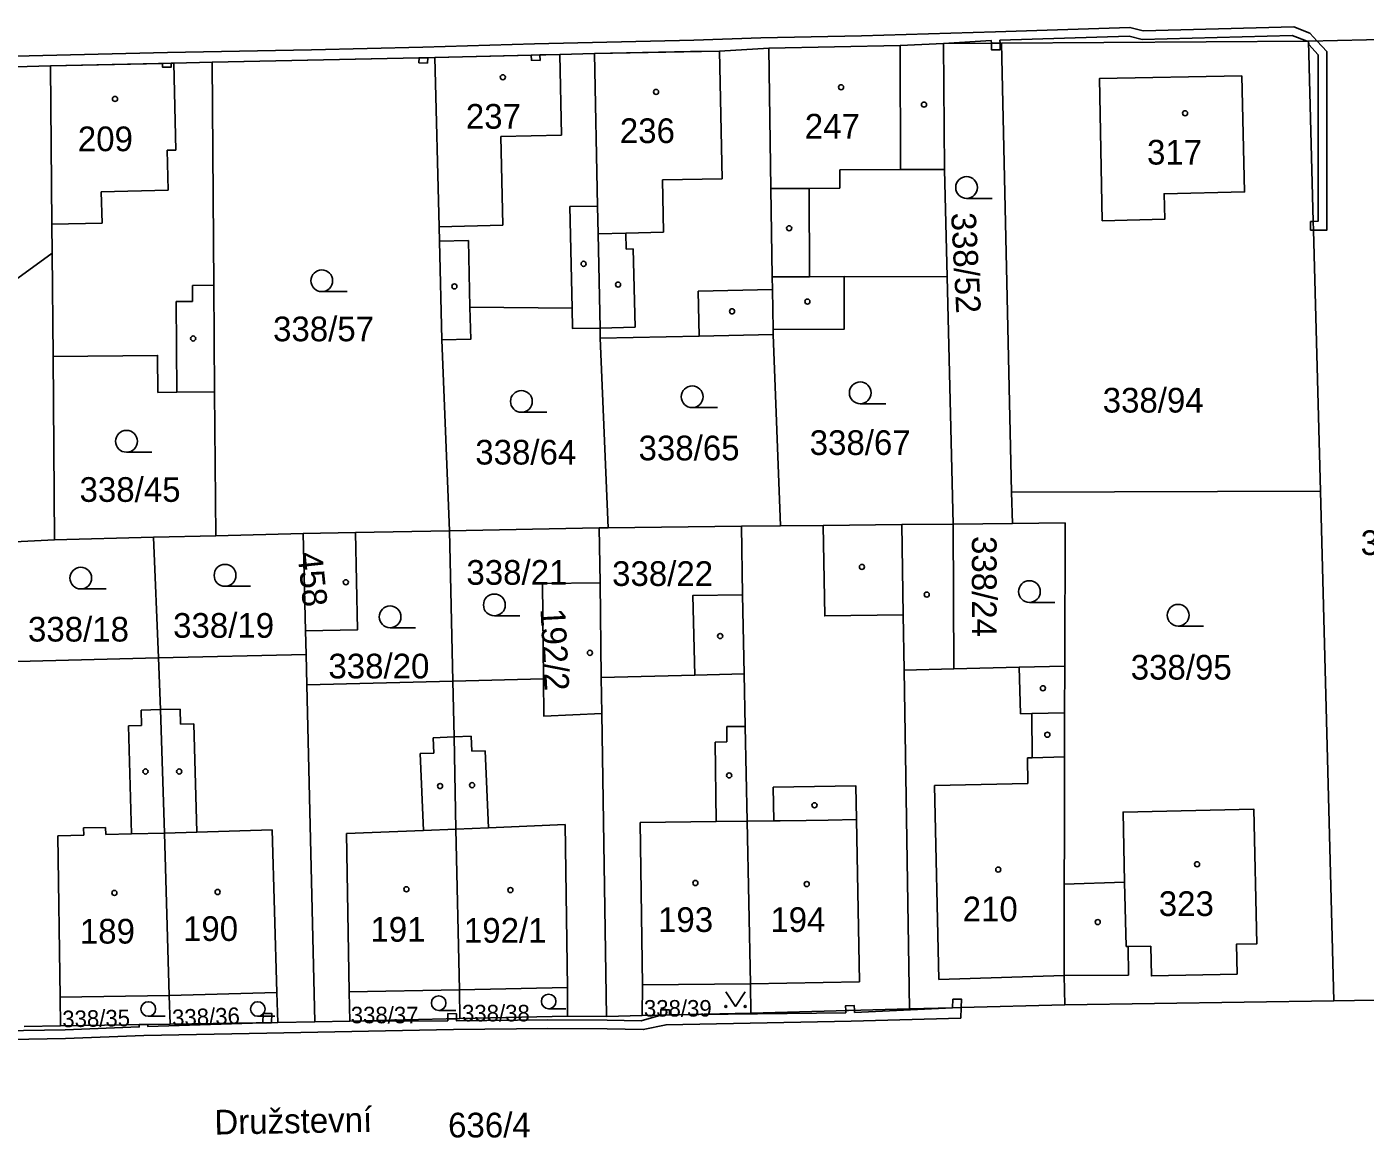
# Model space of a CAD drawing. Extents: x -758582 to -751794, y -998770 to -994350.
# Drawn here: x -755856.2 to -755764, y -995339.9 to -995263.3 of the extents above; entities that cross this region are included whole.
import ezdxf

# ---------------------------------------------------------------- set-up
doc = ezdxf.new("R2010")
doc.units = 0
for name, color, linetype in [('Hranice parcel', 7, 'Continuous'), ('Parcelní čísla', 7, 'Continuous'), ('Pop  PČ popisy', 7, 'Continuous'), ('Vnitřní kresba', 7, 'Continuous'), ('Věcná břemena k části', 7, 'Continuous'), ('Značky budov', 7, 'Continuous'), ('Značky kultur', 7, 'Continuous')]:
    doc.layers.add(name, color=color, linetype=linetype)

msp = doc.modelspace()

# ---------------------------------------------------------------- linework, layer by layer
at = {"layer": 'Hranice parcel'}
for p, q in [((-755755.71, -995264.05), (-755767.91, -995264.33)), ((-755789.06, -995264.46), (-755793.04, -995264.49)), ((-755767.91, -995264.33), (-755789.06, -995264.46)), ((-755788.36, -995295.38), (-755789.06, -995264.46)), ((-755828.06, -995265.45), (-755843.39, -995265.77)), ((-755854.4, -995278.93), (-755854.34, -995286.03)), ((-755792.79, -995280.56), (-755792.37, -995297.58)), ((-755816.68, -995284.08), (-755816.67, -995284.78)), ((-755804.77, -995284.52), (-755804.78, -995284.17)), ((-755827.04, -995298.05), (-755827.58, -995284.89)), ((-755816.12, -995297.84), (-755816.67, -995284.78)), ((-755804.27, -995297.7), (-755804.77, -995284.52)), ((-755854.25, -995298.66), (-755854.34, -995286.03)), ((-755843.14, -995298.39), (-755843.22, -995288.48)), ((-755788.36, -995295.38), (-755767.1, -995295.32)), ((-755788.29, -995297.54), (-755788.36, -995295.38)), ((-755766.18, -995330.42), (-755767.1, -995295.32)), ((-755837.12, -995298.24), (-755843.14, -995298.39)), ((-755833.52, -995298.17), (-755837.12, -995298.24)), ((-755837.12, -995298.24), (-755836.96, -995304.94)), ((-755827.04, -995298.05), (-755833.52, -995298.17)), ((-755816.74, -995297.85), (-755827.04, -995298.05)), ((-755826.82, -995308.39), (-755827.04, -995298.05)), ((-755816.12, -995297.84), (-755816.74, -995297.85)), ((-755816.69, -995301.62), (-755816.74, -995297.85)), ((-755806.96, -995297.73), (-755816.12, -995297.84)), ((-755804.27, -995297.7), (-755806.96, -995297.73)), ((-755806.96, -995297.73), (-755806.87, -995302.46)), ((-755792.37, -995297.58), (-755795.92, -995297.62)), ((-755788.29, -995297.54), (-755792.37, -995297.58)), ((-755854.25, -995298.66), (-755856.99, -995298.8)), ((-755847.42, -995298.49), (-755854.25, -995298.66)), ((-755843.14, -995298.39), (-755847.42, -995298.49)), ((-755847.08, -995306.8), (-755847.42, -995298.49)), ((-755816.69, -995301.62), (-755816.6, -995308.14)), ((-755836.92, -995306.56), (-755836.96, -995304.94)), ((-755847.08, -995306.8), (-755856.82, -995307.05)), ((-755836.92, -995306.56), (-755847.08, -995306.8)), ((-755836.87, -995308.64), (-755836.92, -995306.56)), ((-755784.71, -995310.58), (-755784.7, -995307.36)), ((-755826.82, -995308.39), (-755836.87, -995308.64)), ((-755826.82, -995308.39), (-755820.59, -995308.24)), ((-755816.6, -995308.14), (-755816.56, -995310.63)), ((-755836.33, -995331.87), (-755836.87, -995308.64)), ((-755816.56, -995310.63), (-755816.25, -995331.5)), ((-755784.71, -995313.61), (-755784.71, -995310.58)), ((-755784.74, -995328.68), (-755784.73, -995322.38)), ((-755780.58, -995322.25), (-755784.73, -995322.38)), ((-755806.33, -995329.25), (-755806.3, -995331.26)), ((-755784.69, -995330.7), (-755784.74, -995328.68)), ((-755846.28, -995332.02), (-755846.34, -995330.05)), ((-755826.33, -995331.64), (-755826.37, -995329.66)), ((-755784.69, -995330.7), (-755766.18, -995330.42)), ((-755766.18, -995330.42), (-755753.96, -995330.21)), ((-755816.25, -995331.5), (-755813.79, -995331.42)), ((-755813.79, -995331.42), (-755806.3, -995331.26)), ((-755806.3, -995331.26), (-755795.39, -995330.96)), ((-755856.32, -995332.17), (-755853.83, -995332.13)), ((-755853.83, -995332.13), (-755846.28, -995332.02)), ((-755846.28, -995332.02), (-755838.87, -995331.91)), ((-755838.87, -995331.91), (-755836.33, -995331.87)), ((-755836.33, -995331.87), (-755833.91, -995331.81)), ((-755833.91, -995331.81), (-755826.33, -995331.64)), ((-755826.33, -995331.64), (-755818.93, -995331.46)), ((-755818.93, -995331.46), (-755816.25, -995331.5))]:
    msp.add_line(p, q, dxfattribs=at)
for points in [[(-755805.06, -995264.8), (-755808.47, -995265), (-755817.08, -995265.18)], [(-755793.04, -995264.49), (-755796.03, -995264.61), (-755805.06, -995264.8)], [(-755804.78, -995284.17), (-755804.82, -995281.42), (-755804.83, -995280.56), (-755804.92, -995274.47), (-755805.06, -995264.8)], [(-755792.79, -995280.56), (-755792.97, -995273.15), (-755793.04, -995264.49)], [(-755767.1, -995295.32), (-755767.57, -995277.33), (-755767.59, -995276.74), (-755767.91, -995264.33)], [(-755843.39, -995265.77), (-755846.03, -995265.83), (-755854.52, -995266.03)], [(-755843.22, -995288.48), (-755843.27, -995281.13), (-755843.39, -995265.77)], [(-755817.08, -995265.18), (-755819.46, -995265.24), (-755828.06, -995265.45)], [(-755828.06, -995265.45), (-755827.77, -995277.1), (-755827.75, -995278.1), (-755827.58, -995284.89)], [(-755817.08, -995265.18), (-755816.86, -995275.68), (-755816.82, -995277.58), (-755816.68, -995284.08)], [(-755854.52, -995266.03), (-755860.15, -995266.18), (-755870.93, -995266.46)], [(-755854.4, -995278.93), (-755854.42, -995276.93), (-755854.52, -995266.03)], [(-755772.5, -995266.71), (-755782.3, -995266.89), (-755782.12, -995276.69), (-755777.82, -995276.59), (-755777.86, -995274.83), (-755772.32, -995274.71), (-755772.5, -995266.71)], [(-755870.36, -995288.31), (-755867.15, -995288.2), (-755854.4, -995278.93)], [(-755804.78, -995284.17), (-755799.88, -995284.15), (-755799.89, -995280.54), (-755792.79, -995280.56)], [(-755827.58, -995284.89), (-755825.58, -995284.84), (-755825.64, -995282.64), (-755818.61, -995282.72), (-755818.58, -995284.12), (-755816.68, -995284.08)], [(-755816.67, -995284.78), (-755809.87, -995284.63), (-755804.77, -995284.52)], [(-755854.34, -995286.03), (-755847.14, -995285.96), (-755847.12, -995288.51), (-755845.82, -995288.5), (-755843.22, -995288.48)], [(-755836.96, -995304.94), (-755833.39, -995304.87), (-755833.52, -995298.17)], [(-755795.92, -995297.62), (-755801.32, -995297.67), (-755804.27, -995297.7)], [(-755795.39, -995330.96), (-755795.76, -995307.63), (-755795.82, -995303.82), (-755795.92, -995297.62)], [(-755784.7, -995307.36), (-755787.83, -995307.44), (-755792.33, -995307.55), (-755792.37, -995297.58)], [(-755784.7, -995307.36), (-755784.68, -995297.5), (-755788.29, -995297.54)], [(-755820.59, -995308.24), (-755820.65, -995301.68), (-755816.69, -995301.62)], [(-755806.87, -995302.46), (-755810.29, -995302.49), (-755810.17, -995307.98), (-755816.6, -995308.14)], [(-755806.33, -995329.25), (-755806.56, -995318.04), (-755806.69, -995311.52), (-755806.76, -995307.9), (-755806.87, -995302.46)], [(-755846.34, -995330.05), (-755846.68, -995318.86), (-755846.94, -995310.36), (-755847.08, -995306.8)], [(-755826.37, -995329.66), (-755826.61, -995318.59), (-755826.74, -995312.23), (-755826.82, -995308.39)], [(-755816.56, -995310.63), (-755820.56, -995310.8), (-755820.59, -995308.24)], [(-755784.73, -995322.38), (-755784.72, -995318.96), (-755784.71, -995313.61)], [(-755780.33, -995326.68), (-755778.78, -995326.65), (-755778.73, -995328.7), (-755772.84, -995328.57), (-755772.88, -995326.52), (-755771.48, -995326.49), (-755771.68, -995317.22), (-755780.68, -995317.41), (-755780.58, -995322.25)], [(-755784.74, -995328.68), (-755780.31, -995328.64), (-755780.33, -995326.68)], [(-755818.93, -995331.46), (-755818.92, -995329.49), (-755826.37, -995329.66)], [(-755813.79, -995331.42), (-755813.77, -995329.31), (-755806.33, -995329.25)], [(-755853.83, -995332.13), (-755853.86, -995330.16), (-755846.34, -995330.05)], [(-755846.34, -995330.05), (-755838.93, -995329.84), (-755838.87, -995331.91)], [(-755833.91, -995331.81), (-755833.95, -995329.79), (-755826.37, -995329.66)], [(-755795.39, -995330.96), (-755792.42, -995330.89), (-755791.82, -995330.87), (-755784.69, -995330.7)]]:
    msp.add_lwpolyline(points, dxfattribs=at)
at = {"layer": 'Vnitřní kresba'}
for p, q in [((-755808.29, -995273.8), (-755808.47, -995265)), ((-755796.03, -995264.61), (-755796, -995273.17)), ((-755845.89, -995271.83), (-755846.03, -995265.83)), ((-755819.46, -995265.24), (-755819.33, -995270.79)), ((-755819.33, -995270.79), (-755823.52, -995270.89)), ((-755823.52, -995270.89), (-755823.37, -995276.99)), ((-755846.49, -995271.84), (-755845.89, -995271.83)), ((-755846.42, -995274.59), (-755846.49, -995271.84)), ((-755800.17, -995273.18), (-755796, -995273.17)), ((-755800.17, -995274.45), (-755800.17, -995273.18)), ((-755796, -995273.17), (-755792.97, -995273.15)), ((-755812.39, -995273.88), (-755808.29, -995273.8)), ((-755812.31, -995277.48), (-755812.39, -995273.88)), ((-755851.02, -995274.7), (-755846.42, -995274.59)), ((-755850.97, -995276.85), (-755851.02, -995274.7)), ((-755804.92, -995274.47), (-755802.29, -995274.46)), ((-755802.29, -995274.46), (-755800.17, -995274.45)), ((-755802.27, -995280.55), (-755802.29, -995274.46)), ((-755816.86, -995275.68), (-755818.76, -995275.72)), ((-755818.61, -995282.72), (-755818.76, -995275.72)), ((-755854.42, -995276.93), (-755850.97, -995276.85)), ((-755823.37, -995276.99), (-755827.77, -995277.1)), ((-755816.82, -995277.58), (-755814.91, -995277.54)), ((-755814.91, -995277.54), (-755812.31, -995277.48)), ((-755814.89, -995278.64), (-755814.91, -995277.54)), ((-755825.75, -995278.05), (-755827.75, -995278.1)), ((-755825.64, -995282.64), (-755825.75, -995278.05)), ((-755814.89, -995278.64), (-755814.4, -995278.63)), ((-755814.4, -995278.63), (-755814.28, -995284.02)), ((-755804.83, -995280.56), (-755802.27, -995280.55)), ((-755799.89, -995280.54), (-755802.27, -995280.55)), ((-755843.27, -995281.13), (-755844.75, -995281.14)), ((-755844.75, -995281.14), (-755844.74, -995282.24)), ((-755804.82, -995281.42), (-755809.93, -995281.53)), ((-755809.93, -995281.53), (-755809.87, -995284.63)), ((-755844.74, -995282.24), (-755845.87, -995282.25)), ((-755845.87, -995282.25), (-755845.82, -995288.5)), ((-755814.28, -995284.02), (-755816.68, -995284.08)), ((-755787.83, -995307.44), (-755787.74, -995310.64)), ((-755810.17, -995307.98), (-755806.76, -995307.9)), ((-755792.33, -995307.55), (-755795.76, -995307.63)), ((-755848.28, -995310.4), (-755846.94, -995310.36)), ((-755848.25, -995311.45), (-755848.28, -995310.4)), ((-755846.94, -995310.36), (-755845.59, -995310.32)), ((-755845.59, -995310.32), (-755845.56, -995311.37)), ((-755787.74, -995310.64), (-755786.97, -995310.62)), ((-755786.97, -995310.62), (-755784.71, -995310.58)), ((-755786.97, -995310.62), (-755786.95, -995313.68)), ((-755849.15, -995311.47), (-755848.25, -995311.45)), ((-755848.94, -995318.92), (-755849.15, -995311.47)), ((-755845.56, -995311.37), (-755844.66, -995311.34)), ((-755844.66, -995311.34), (-755844.45, -995318.79)), ((-755807.97, -995311.52), (-755807.96, -995312.58)), ((-755807.97, -995311.52), (-755806.69, -995311.52)), ((-755828.18, -995312.3), (-755826.74, -995312.23)), ((-755828.18, -995312.3), (-755828.14, -995313.35)), ((-755826.74, -995312.23), (-755825.55, -995312.18)), ((-755825.55, -995312.18), (-755825.51, -995313.23)), ((-755807.96, -995312.58), (-755808.77, -995312.6)), ((-755808.77, -995312.6), (-755808.69, -995318.06)), ((-755828.14, -995313.35), (-755829.06, -995313.38)), ((-755829.06, -995313.38), (-755828.84, -995318.68)), ((-755825.51, -995313.23), (-755824.59, -995313.19)), ((-755824.59, -995313.19), (-755824.37, -995318.49)), ((-755786.95, -995313.68), (-755787.27, -995313.68)), ((-755787.27, -995313.68), (-755787.24, -995315.44)), ((-755786.95, -995313.68), (-755784.71, -995313.61)), ((-755804.76, -995315.71), (-755804.72, -995318.02)), ((-755787.24, -995315.44), (-755793.67, -995315.59)), ((-755793.37, -995328.94), (-755793.67, -995315.59)), ((-755852.24, -995318.51), (-755850.72, -995318.47)), ((-755852.22, -995319.01), (-755852.24, -995318.51)), ((-755850.72, -995318.47), (-755850.7, -995318.97)), ((-755826.61, -995318.59), (-755824.37, -995318.49)), ((-755819.08, -995318.27), (-755824.37, -995318.49)), ((-755818.92, -995329.49), (-755819.08, -995318.27)), ((-755808.69, -995318.06), (-755813.93, -995318.13)), ((-755813.77, -995329.31), (-755813.93, -995318.13)), ((-755808.69, -995318.06), (-755806.56, -995318.04)), ((-755804.72, -995318.02), (-755806.56, -995318.04)), ((-755804.72, -995318.02), (-755804.28, -995318.02)), ((-755799.04, -995317.92), (-755798.82, -995329.1)), ((-755854.02, -995319.06), (-755852.22, -995319.01)), ((-755854.02, -995319.06), (-755853.86, -995330.16)), ((-755850.7, -995318.97), (-755848.94, -995318.92)), ((-755848.94, -995318.92), (-755846.68, -995318.86)), ((-755846.68, -995318.86), (-755844.45, -995318.79)), ((-755844.45, -995318.79), (-755839.25, -995318.64)), ((-755839.25, -995318.64), (-755838.93, -995329.84)), ((-755834.14, -995318.9), (-755828.84, -995318.68)), ((-755834.14, -995318.9), (-755833.95, -995329.79)), ((-755828.84, -995318.68), (-755826.61, -995318.59)), ((-755780.48, -995326.68), (-755780.58, -995322.25)), ((-755780.48, -995326.68), (-755780.33, -995326.68)), ((-755806.33, -995329.25), (-755798.82, -995329.1)), ((-755784.74, -995328.68), (-755793.37, -995328.94))]:
    msp.add_line(p, q, dxfattribs=at)
for points in [[(-755795.82, -995303.82), (-755801.22, -995303.91), (-755801.32, -995297.67)], [(-755799.04, -995317.92), (-755799.09, -995315.6), (-755804.76, -995315.71)], [(-755804.28, -995318.02), (-755802.5, -995317.99), (-755800.99, -995317.96), (-755799.04, -995317.92)]]:
    msp.add_lwpolyline(points, dxfattribs=at)
at = {"layer": 'Věcná břemena k části'}
for points in [[(-755860.15, -995266.18), (-755854.52, -995266.03), (-755846.8, -995265.85), (-755846.2, -995265.83), (-755846.03, -995265.83), (-755843.39, -995265.77), (-755829.14, -995265.47), (-755828.54, -995265.46), (-755828.06, -995265.45), (-755821.43, -995265.29), (-755820.83, -995265.27), (-755819.46, -995265.24), (-755817.08, -995265.18), (-755810.46, -995265.04), (-755809.86, -995265.03), (-755808.47, -995265), (-755805.06, -995264.8), (-755796.03, -995264.61), (-755793.04, -995264.49), (-755789.76, -995264.28), (-755789.75, -995264.47), (-755789.15, -995264.46), (-755789.16, -995264.26), (-755780.27, -995263.98), (-755779.36, -995264.21), (-755769.05, -995263.93), (-755768.02, -995264.33), (-755767.91, -995264.33), (-755767.9, -995264.56), (-755767.26, -995265.27), (-755767.26, -995276.73), (-755767.59, -995276.74), (-755767.57, -995277.33), (-755766.66, -995277.34), (-755766.66, -995265.04), (-755767.32, -995264.32), (-755767.82, -995263.77), (-755768.94, -995263.33), (-755779.29, -995263.61), (-755780.21, -995263.37), (-755789.47, -995263.67), (-755798.68, -995263.96), (-755805.63, -995264.09), (-755810.22, -995264.25), (-755821.21, -995264.51), (-755828.89, -995264.74), (-755836.55, -995264.91), (-755846.47, -995265.11), (-755860.77, -995265.44)], [(-755791.85, -995331.6), (-755791.82, -995330.87), (-755792.42, -995330.89), (-755799.17, -995331.21), (-755799.17, -995331.06), (-755799.77, -995331.08), (-755799.77, -995331.23), (-755811.91, -995331.38), (-755812.51, -995331.39), (-755813.86, -995331.79), (-755816.19, -995331.75), (-755820.29, -995331.72), (-755826.57, -995331.78), (-755826.57, -995331.65), (-755827.17, -995331.66), (-755827.17, -995331.79), (-755833.91, -995331.81), (-755836.33, -995331.87), (-755838.87, -995331.91), (-755839.31, -995331.92), (-755839.91, -995331.93), (-755847.81, -995332.19), (-755847.81, -995332.04), (-755848.41, -995332.05), (-755848.41, -995332.21), (-755853.5, -995332.4), (-755862.11, -995332.55)], [(-755853.48, -995333), (-755848.09, -995332.79), (-755839.63, -995332.63), (-755826.77, -995332.38), (-755820.29, -995332.32), (-755816.2, -995332.35), (-755813.71, -995332.39), (-755812.14, -995332.06), (-755799.39, -995331.82), (-755791.85, -995331.6)], [(-755904.61, -995342.37), (-755904.86, -995335.72), (-755905.71, -995334.02), (-755904.04, -995334.02), (-755891.45, -995333.81), (-755886.34, -995333.63), (-755875.7, -995333.36), (-755870.14, -995333.28), (-755862.36, -995333.16), (-755853.48, -995333)]]:
    msp.add_lwpolyline(points, dxfattribs=at)
for points in [[(-755789.15, -995264.46), (-755789.75, -995264.47), (-755789.75, -995264.91), (-755789.15, -995264.91)], [(-755846.2, -995265.83), (-755846.8, -995265.85), (-755846.8, -995266.12), (-755846.2, -995266.11)], [(-755828.56, -995265.83), (-755828.54, -995265.46), (-755829.14, -995265.47), (-755829.16, -995265.81)], [(-755820.83, -995265.27), (-755821.43, -995265.29), (-755821.41, -995265.64), (-755820.81, -995265.65)], [(-755767.77, -995276.74), (-755767.78, -995277.33), (-755767.57, -995277.33), (-755767.59, -995276.74)], [(-755792.42, -995330.89), (-755791.82, -995330.87), (-755791.8, -995330.31), (-755792.4, -995330.31)], [(-755839.88, -995331.28), (-755839.91, -995331.93), (-755839.31, -995331.92), (-755839.28, -995331.29)], [(-755827.17, -995331.29), (-755827.17, -995331.66), (-755826.57, -995331.65), (-755826.57, -995331.3)], [(-755812.51, -995331.39), (-755811.91, -995331.38), (-755811.91, -995331.04), (-755812.51, -995331.03)], [(-755799.17, -995331.06), (-755799.19, -995330.74), (-755799.79, -995330.75), (-755799.77, -995331.08)]]:
    msp.add_lwpolyline(points, close=True, dxfattribs=at)
at = {"layer": 'Značky budov'}
for centre in [(-755823.377, -995266.809), (-755812.827, -995267.819), (-755800.097, -995267.499), (-755850.077, -995268.299), (-755794.387, -995268.689), (-755776.417, -995269.289), (-755803.667, -995277.209), (-755817.817, -995279.659), (-755826.717, -995281.209), (-755815.447, -995281.089), (-755802.417, -995282.259), (-755807.597, -995282.929), (-755844.697, -995284.799), (-755798.657, -995300.529), (-755834.187, -995301.589), (-755794.197, -995302.439), (-755808.417, -995305.289), (-755817.387, -995306.449), (-755786.197, -995308.889), (-755785.897, -995312.089), (-755847.977, -995314.619), (-755845.657, -995314.619), (-755807.797, -995314.889), (-755827.697, -995315.619), (-755825.497, -995315.559), (-755801.927, -995316.949), (-755789.277, -995321.379), (-755775.587, -995321.009), (-755810.127, -995322.299), (-755802.457, -995322.369), (-755850.117, -995322.979), (-755843.017, -995322.919), (-755830.017, -995322.729), (-755822.857, -995322.789), (-755782.427, -995324.989)]:
    msp.add_circle(centre, 0.175, dxfattribs=at)
at = {"layer": 'Značky kultur'}
for p, q in [((-755791.453, -995275.15), (-755789.703, -995275.15)), ((-755835.843, -995281.57), (-755834.093, -995281.57)), ((-755822.103, -995289.88), (-755820.353, -995289.88)), ((-755810.343, -995289.56), (-755808.593, -995289.56)), ((-755798.773, -995289.29), (-755797.023, -995289.29)), ((-755849.283, -995292.63), (-755847.533, -995292.63)), ((-755842.503, -995301.86), (-755840.753, -995301.86)), ((-755852.433, -995302.05), (-755850.683, -995302.05)), ((-755787.133, -995302.98), (-755785.383, -995302.98)), ((-755823.963, -995303.9), (-755822.213, -995303.9)), ((-755776.893, -995304.61), (-755775.143, -995304.61)), ((-755831.143, -995304.72), (-755829.393, -995304.72)), ((-755827.795, -995331.07), (-755826.623, -995331.07)), ((-755820.225, -995330.96), (-755819.053, -995330.96)), ((-755847.785, -995331.48), (-755846.613, -995331.48)), ((-755840.245, -995331.48), (-755839.073, -995331.48))]:
    msp.add_line(p, q, dxfattribs=at)
msp.add_lwpolyline([(-755808.03, -995329.794), (-755807.36, -995330.8), (-755806.69, -995329.794)], dxfattribs=at)
for centre, radius in [((-755791.453, -995274.4), 0.75), ((-755835.843, -995280.82), 0.75), ((-755810.343, -995288.81), 0.75), ((-755798.773, -995288.54), 0.75), ((-755822.103, -995289.13), 0.75), ((-755849.283, -995291.88), 0.75), ((-755852.433, -995301.3), 0.75), ((-755842.503, -995301.11), 0.75), ((-755787.133, -995302.23), 0.75), ((-755823.963, -995303.15), 0.75), ((-755831.143, -995303.97), 0.75), ((-755776.893, -995303.86), 0.75), ((-755847.785, -995330.977), 0.502), ((-755840.245, -995330.977), 0.502), ((-755827.795, -995330.567), 0.502), ((-755820.225, -995330.457), 0.502), ((-755808.03, -995330.8), 0.067), ((-755806.69, -995330.8), 0.067)]:
    msp.add_circle(centre, radius, dxfattribs=at)

# ---------------------------------------------------------------- texts
at = {"layer": 'Parcelní čísla'}
for s, height, p in [('237', 1.7, (-755825.925, -995270.35)), ('236', 1.7, (-755815.325, -995271.34)), ('247', 1.7, (-755802.595, -995271.03)), ('209', 1.7, (-755852.635, -995271.9)), ('317', 1.7, (-755779.035, -995272.82)), ('338/57', 1.7, (-755839.197, -995284.99)), ('338/94', 1.7, (-755782.087, -995289.9)), ('338/64', 1.7, (-755825.277, -995293.48)), ('338/65', 1.7, (-755814.037, -995293.19)), ('338/67', 1.7, (-755802.257, -995292.82)), ('338/45', 1.7, (-755852.517, -995296.05)), ('340/1', 1.7, (-755764.328, -995299.71)), ('338/21', 1.7, (-755825.887, -995301.76)), ('338/22', 1.7, (-755815.857, -995301.84)), ('338/19', 1.7, (-755846.077, -995305.41)), ('338/18', 1.7, (-755856.067, -995305.67)), ('338/20', 1.7, (-755835.387, -995308.21)), ('338/95', 1.7, (-755780.157, -995308.29)), ('323', 1.7, (-755778.225, -995324.57)), ('193', 1.7, (-755812.695, -995325.67)), ('194', 1.7, (-755804.965, -995325.67)), ('210', 1.7, (-755791.725, -995324.94)), ('189', 1.7, (-755852.495, -995326.47)), ('190', 1.7, (-755845.395, -995326.29)), ('191', 1.7, (-755832.495, -995326.34)), ('192/1', 1.7, (-755826.058, -995326.41)), ('338/39', 1.14, (-755813.667, -995331.5)), ('338/37', 1.14, (-755833.847, -995331.96)), ('338/38', 1.14, (-755826.187, -995331.83)), ('636/4', 1.7, (-755827.148, -995339.82))]:
    msp.add_text(s, height=height, dxfattribs=at).set_placement(p)
for s, height, rotation, p in [('338/52', 1.7, 273, (-755792.525, -995276.162)), ('338/24', 1.7, 270, (-755791.09, -995298.402)), ('458', 1.7, 276, (-755837.518, -995299.576)), ('192/2', 1.7, 273, (-755820.791, -995303.42)), ('338/35', 1.14, 1, (-755853.696, -995332.236)), ('338/36', 1.14, 2, (-755846.125, -995332.162))]:
    msp.add_text(s, height=height, rotation=rotation, dxfattribs=at).set_placement(p)
at = {"layer": 'Pop  PČ popisy'}
msp.add_text('Družstevní', height=1.7, rotation=1, dxfattribs=at).set_placement((-755843.222, -995339.627))

doc.saveas('drawing.dxf')
